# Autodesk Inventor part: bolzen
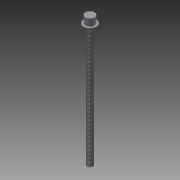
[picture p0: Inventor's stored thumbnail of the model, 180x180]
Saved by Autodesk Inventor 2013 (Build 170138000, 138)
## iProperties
Created: 2012-11
Part Number: bolzen
Material: Allgemein
Document SubType Name: Modeling
Designer: macuser
Density: 1 g/cm^3
Author: macuser
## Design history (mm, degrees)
sketch "Skizze1"
  geometry: L1 (0, -74.4)-(0, 446.4) reference; L2 (21.6, 0)-(-3.6, 0) reference; L3 (0, 0)-(8, 0); L4 (8, 0)-(8, 350); L5 (8, 350)-(18, 350); L6 (18, 350)-(18, 352); L7 (18, 352)-(13, 352); L8 (13, 352)-(13, 372); L9 (13, 372)-(0, 372); L10 (0, 372)-(0, 0)
  constraints: 16 end point, 4 perpendicular, 2 parallel, 2 point on line, 1 collinear
  dimensions: "d0" = 8 distance of L3.start L3.end; "d1" = 350 distance of L3.end L4.end; "d2" = 10 distance of L4.end L5.end; "d3" = 2 distance of L5.end L6.end; "d4" = 5 distance of L6.end L7.end; "d5" = 20 distance of L7.end L8.end
revolve "Umdrehung1" sketch "Skizze1" stored, may be unused: angle "d6" = 90 deg
feature "Gewinde1" dims "d7" = 10, "d8" = 0
node "Volumenkörper1"
